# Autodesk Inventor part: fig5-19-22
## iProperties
Created: 2004-05
Part Number: fig5-19-22
Document SubType Name: Modeling
Designer: CADCIM Technologies
Manufacturer: Standard
Standards Organization: Custom
Author: CADCIM Technologies
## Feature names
1. Extrusion1
2. Fillet1
